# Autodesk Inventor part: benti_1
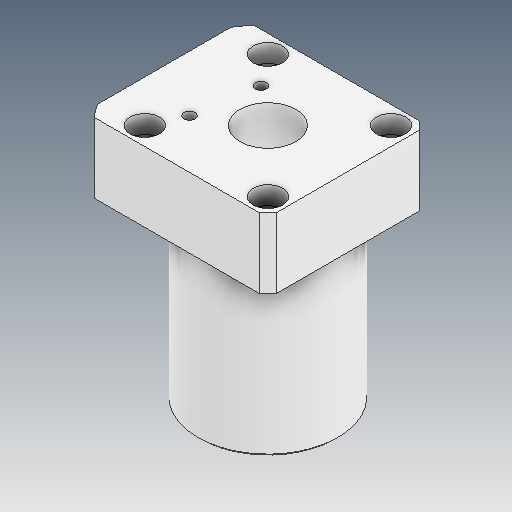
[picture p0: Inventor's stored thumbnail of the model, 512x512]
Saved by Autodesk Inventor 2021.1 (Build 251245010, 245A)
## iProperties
Created: 2021-05
Part Number: benti_1
Material: Ogólny
Document SubType Name: Modeling
Designer: user
Density: 1 g/cm^3
Appearance: Domyślna
Author: user
Revision Number: ÈÎºÎ
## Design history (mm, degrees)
feature "µ¹½Ç2"
node "Bryła1"
